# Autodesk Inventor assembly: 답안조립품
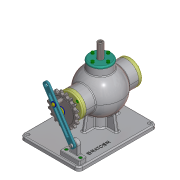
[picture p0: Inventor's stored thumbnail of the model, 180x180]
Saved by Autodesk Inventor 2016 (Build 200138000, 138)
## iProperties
Created: 2017-07
Part Number: 답안조립품
Document SubType Name: Assembly
Designer: KSEW
Mass: 3277.36 g
Surface Area: 2432.29 cm^2
Volume: 944.5 cm^3
Density: 3.46994 g/cm^3
Author: KSEW
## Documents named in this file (20)
- D:\370707V1005\답안조립품.iam
- D:\370707V1005\본체.ipt
- D:\370707V1005\고정핀.ipt
- D:\370707V1005\너트 M8x1.ipt
- D:\370707V1005\둥근머리 볼트 M4x8.ipt
- D:\370707V1005\뒤커버.ipt
- D:\370707V1005\베어링 6202.ipt
- D:\370707V1005\본체커버.ipt
- D:\370707V1005\볼트 M4x12.ipt
- D:\370707V1005\스프로킷.ipt
- D:\370707V1005\스프링.ipt
- D:\370707V1005\슬라이드 커버.ipt
- D:\370707V1005\슬라이드.ipt
- D:\370707V1005\앞커버.ipt
- D:\370707V1005\연결대.ipt
- D:\370707V1005\오일실.ipt
- D:\370707V1005\와셔 8x17.ipt
- D:\370707V1005\와셔 ISO 7093 A.ipt
- D:\370707V1005\축.ipt
- D:\370707V1005\키 3 x 3 x 12.ipt
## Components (1 placed, 1 different names)
1. 고정핀:1 — 각도:4, 각도:6, 각도:7
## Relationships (3: Angle 3)
- 각도:4 [Angle]: 고정핀:1
- 각도:6 [Angle]: 고정핀:1
- 각도:7 [Angle]: 고정핀:1
